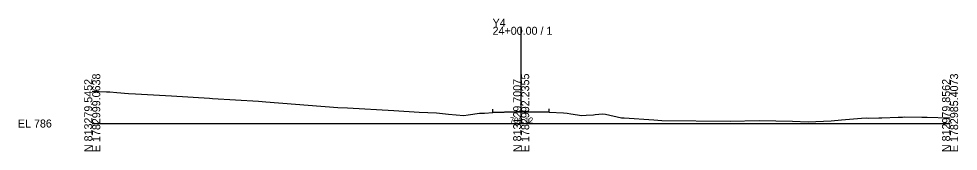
# Model space of a CAD drawing. Extents: x -26 to 3903, y -10 to 9562.
# Drawn here: x 3574.3 to 3902.8, y 490.3 to 536.7 of the extents above; entities that cross this region are included whole.
import ezdxf

# ---------------------------------------------------------------- set-up
doc = ezdxf.new("R2010")
doc.units = 0
for name, color, linetype in [('Exist Cross Section Cell', 7, 'Continuous'), ('Exist XS Center Line Elevation Label', 7, 'Continuous'), ('Exist XS Ground Line', 7, 'Continuous'), ('Prop XS EOT Tick Mark', 7, 'Continuous'), ('Prop XS Finish Grade Pavement', 7, 'Continuous')]:
    doc.layers.add(name, color=color, linetype=linetype)

msp = doc.modelspace()

# ---------------------------------------------------------------- linework, layer by layer
at = {"layer": 'Exist Cross Section Cell'}
for p, q in [((3750, 500), (3750, 533.86)), ((3600, 500), (3750, 500)), ((3750, 500), (3900, 500))]:
    msp.add_line(p, q, dxfattribs=at)
at = {"layer": 'Exist XS Ground Line'}
for p, q in [((3600, 511.29), (3604.96, 511.04)), ((3604.96, 511.04), (3606.19, 511.08)), ((3606.19, 511.08), (3608.57, 510.86)), ((3608.57, 510.86), (3612.67, 510.53)), ((3612.67, 510.53), (3615.08, 510.35)), ((3615.08, 510.35), (3617.2, 510.25)), ((3617.2, 510.25), (3627.7, 509.64)), ((3627.7, 509.64), (3640.95, 508.84)), ((3640.95, 508.84), (3642, 508.78)), ((3642, 508.78), (3658.15, 507.8)), ((3658.15, 507.8), (3660.72, 507.55)), ((3660.72, 507.55), (3685.91, 505.57)), ((3685.91, 505.57), (3689.26, 505.45)), ((3689.26, 505.45), (3705.42, 504.59)), ((3705.42, 504.59), (3714.3, 503.94)), ((3714.3, 503.94), (3720.43, 503.71)), ((3720.43, 503.71), (3724.57, 503.31)), ((3724.57, 503.31), (3727.21, 503.04)), ((3727.21, 503.04), (3729.98, 502.86)), ((3729.98, 502.86), (3731.51, 503.06)), ((3731.51, 503.06), (3735.39, 503.66)), ((3735.39, 503.66), (3737.14, 503.66)), ((3737.14, 503.66), (3740.07, 503.88)), ((3740.07, 503.88), (3748.09, 504.06)), ((3748.09, 504.06), (3749.82, 504.12)), ((3749.82, 504.12), (3752.67, 504.08)), ((3752.67, 504.08), (3759.78, 503.99)), ((3759.78, 503.99), (3764.82, 503.76)), ((3764.82, 503.76), (3766.11, 503.68)), ((3766.11, 503.68), (3767.35, 503.34)), ((3767.35, 503.34), (3771.24, 502.76)), ((3771.24, 502.76), (3772.71, 502.92)), ((3772.71, 502.92), (3775.26, 503.05)), ((3775.26, 503.05), (3775.85, 503.15)), ((3775.85, 503.15), (3778.48, 503.42)), ((3778.48, 503.42), (3779.45, 503.32)), ((3779.45, 503.32), (3785.07, 502.05)), ((3785.07, 502.05), (3786.04, 501.94)), ((3786.04, 501.94), (3796.44, 501.33)), ((3796.44, 501.33), (3799.17, 501.05)), ((3799.17, 501.05), (3823.08, 500.85)), ((3823.08, 500.85), (3833.22, 501.05)), ((3833.22, 501.05), (3844.92, 500.83)), ((3844.92, 500.83), (3850.41, 500.57)), ((3850.41, 500.57), (3858.42, 500.91)), ((3858.42, 500.91), (3862.05, 501.26)), ((3862.05, 501.26), (3869.04, 501.89)), ((3869.04, 501.89), (3870.75, 501.95)), ((3870.75, 501.95), (3871.31, 501.92)), ((3871.31, 501.92), (3875.06, 501.94)), ((3875.06, 501.94), (3876.13, 501.95)), ((3876.13, 501.95), (3881.87, 502.18)), ((3881.87, 502.18), (3883.31, 502.24)), ((3883.31, 502.24), (3884.22, 502.29)), ((3884.22, 502.29), (3890.17, 502.24)), ((3890.17, 502.24), (3892.02, 502.22)), ((3892.02, 502.22), (3899.58, 501.99)), ((3899.58, 501.99), (3900, 501.97))]:
    msp.add_line(p, q, dxfattribs=at)
at = {"layer": 'Prop XS EOT Tick Mark'}
for p, q in [((3740.07, 504), (3740.07, 505)), ((3759.78, 504.11), (3759.78, 505.11))]:
    msp.add_line(p, q, dxfattribs=at)
at = {"layer": 'Prop XS Finish Grade Pavement'}
for p, q in [((3740.07, 504), (3748.08, 504.18)), ((3748.08, 504.18), (3749.82, 504.25)), ((3749.82, 504.25), (3752.67, 504.21)), ((3752.67, 504.21), (3759.78, 504.11))]:
    msp.add_line(p, q, dxfattribs=at)

# ---------------------------------------------------------------- texts
at = {"layer": 'Exist Cross Section Cell'}
for s, p in [('Y4', (3740, 533.86)), ('24+00.00 / 1', (3740, 531.06)), ('EL 786', (3574, 498.6))]:
    msp.add_text(s, height=2.8, dxfattribs=at).set_placement(p)
for s, p in [('E 1782999.0638', (3602.8, 490)), ('E 1782992.2355', (3752.8, 490)), ('E 1782985.4073', (3902.8, 490)), ('N 813279.5452', (3600, 490)), ('N 813129.7007', (3750, 490)), ('N 812979.8562', (3900, 490))]:
    msp.add_text(s, height=2.8, rotation=90, dxfattribs=at).set_placement(p)
at = {"layer": 'Exist XS Center Line Elevation Label'}
msp.add_text('790.12', height=2, dxfattribs=at).set_placement((3746.03, 500.12))

doc.saveas('drawing.dxf')
